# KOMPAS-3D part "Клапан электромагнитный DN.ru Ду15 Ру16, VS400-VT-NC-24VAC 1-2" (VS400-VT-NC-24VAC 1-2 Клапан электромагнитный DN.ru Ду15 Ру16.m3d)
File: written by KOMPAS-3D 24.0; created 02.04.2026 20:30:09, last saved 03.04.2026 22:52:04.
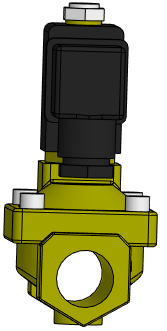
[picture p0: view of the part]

Document properties: Автор: artio; Полное имя файла: C:\Users\artio\OneDrive\Рабочий стол\Клапан электромагнитный DN.ru\VS400-VT-NC\VS400-VT-NC-24VAC 1-2 Клапан электромагнитный DN.ru Ду15 Ру16.m3d

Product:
- Body: Тело 1  | qty 1
    Масса: 1.030062
- Part/product: Клапан электромагнитный DN.ru Ду15 Ру16  | designation VS400-VT-NC-24VAC 1-2
    Масса: 0.759
    Раздел спецификации: Прочие изделия
    Примечание: D130-05633
    additional columns: ef56311e-7521-43dc-8291-0e6108b3d81d; VS400-ET-NC-220VAC 1-2; artio; c; Шероховатость не задана; Да

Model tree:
1. Операция без истории:1

Expressions: VS400-VT-NC-24VAC 1-2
